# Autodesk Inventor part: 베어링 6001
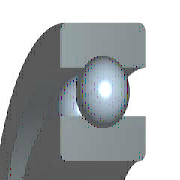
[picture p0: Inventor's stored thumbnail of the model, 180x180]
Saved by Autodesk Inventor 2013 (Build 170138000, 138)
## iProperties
IsCustomPart: 0
Created: 2015-10
Part Number: 베어링 6001
Material: 강철, 연강
Description: 깊은 그루브 볼 베어링
Document SubType Name: Modeling
Standard: KS B 2023
Designer: mdu
Standards Organization: KS
Language: ko-KR
Size Designation: 6001 - 12 x 28 x 8
Categories: <MemberInstance><Categories><Category DisplayName="샤프트 부품" InternalName="7f7aeb1f-a693-4053-b835-cee3144e0d98" Mnemonic="SHFT"><Category DisplayName="베어링" Inter
Density: 7.86 g/cm^3
Mass: 21.4855 g
Surface Area: 31.1809 cm^2
Volume: 2.73352 cm^3
Author: mdu
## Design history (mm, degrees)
sketch "스케치" dims "d0" = 4.16 (= -0.26 x WD + 0.26 x BD)
  geometry: L1 (1.92, 10)-(6.08, 10); L2 (4, 10)-(4, 7.92); L3 (4, 10)-(4, 12.08); L4 (2.454, 8.608)-(0, 8.608); L5 (0, 6)-(8, 6); L6 (2.454, 11.392)-(0, 11.392); L7 (0, 14)-(8, 14); L8 (8, 6)-(8, 8.608); L9 (5.546, 8.608)-(8, 8.608); L10 (5.546, 11.392)-(8, 11.392); L11 (8, 14)-(8, 11.392); L12 (-1.4, 0)-(8.4, 0) reference; L13 (0, -0.3)-(0, 5.3) reference
  constraints: 22 end point, 4 point on line, 2 collinear, 2 perpendicular, 2 symmetric about line, 1 midpoint, 1 parallel, 14 other
  dimensions: "d9" = 12 diameter of L5 L12 (= WD); "d11" = 28 diameter of L7 L12 (= BD); "d12" = 8 distance between parallel lines of L8 L13 (= KB); "d13" = 17.216 diameter of L9 L12 (= 0.326 x BD + 0.674 x WD)
revolve "본체" stored, may be unused: angle "d6" = 90 deg
revolve "볼" stored, may be unused: angle "d7" = 90 deg
pattern_circular "IDS_ARRAYBALL[SIMPL:T]" dims angle "d3" = 360 deg
body "Solid1"
fillet "모깎기1" dims "d1" = 0.3 (= KRS)
other parameters: "WD" = 12 [user parameter; used in 5 equation terms], "BD" = 28 [user parameter; used in 5 equation terms], "KB" = 8 [user parameter; used in 1 equation term], "KRS" = 0.3 [user parameter; used in 1 equation term], "d4" = 0, "d5" = 0, "d8" = 0, "d14" = 0, "d15" = 0, "BBA" = 0 [user parameter], "BC0" = 2360000 [user parameter], "BC" = 5070000 [user parameter], "BR" = 14 (= 0.5 x BD) [user parameter], "WR" = 6 (= 0.5 x WD) [user parameter]
